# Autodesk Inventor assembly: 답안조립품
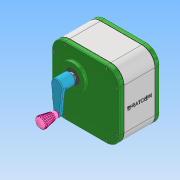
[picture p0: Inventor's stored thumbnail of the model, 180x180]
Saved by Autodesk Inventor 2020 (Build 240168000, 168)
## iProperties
Created: 2022-03
Part Number: 답안조립품
Document SubType Name: Assembly
Designer: Administrator
Mass: 4441.38 g
Surface Area: 3085.81 cm^2
Volume: 1260.3 cm^3
Density: 3.52406 g/cm^3
Author: Administrator
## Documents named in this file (14)
- C:\Users\Administrator\Documents\Inventor\620306V1021\답안조립품.iam
- C:\Users\Administrator\Documents\Inventor\620306V1021\620306V1021\개스킷.ipt
- C:\Users\Administrator\Documents\Inventor\620306V1021\620306V1021\뒤커버.ipt
- C:\Users\Administrator\Documents\Inventor\620306V1021\620306V1021\메인축.ipt
- C:\Users\Administrator\Documents\Inventor\620306V1021\620306V1021\베어링 608.ipt
- C:\Users\Administrator\Documents\Inventor\620306V1021\620306V1021\베어링 6003.ipt
- C:\Users\Administrator\Documents\Inventor\620306V1021\620306V1021\본체.ipt
- C:\Users\Administrator\Documents\Inventor\620306V1021\620306V1021\볼트 M4.ipt
- C:\Users\Administrator\Documents\Inventor\620306V1021\620306V1021\서브축.ipt
- C:\Users\Administrator\Documents\Inventor\620306V1021\620306V1021\손잡이A.ipt
- C:\Users\Administrator\Documents\Inventor\620306V1021\620306V1021\손잡이B.ipt
- C:\Users\Administrator\Documents\Inventor\620306V1021\620306V1021\앞커버.ipt
- C:\Users\Administrator\Documents\Inventor\620306V1021\620306V1021\오일실 8 x 22 x 7.ipt
- C:\Users\Administrator\Documents\Inventor\620306V1021\620306V1021\오일실 17 x 32 x 8.ipt
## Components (2 placed, 1 different names)
1. 개스킷:1
2. 개스킷:2
## Component patterns: 구성요소 패턴 1:2 (2 elements), 구성요소 패턴 3:2 (2 elements)
